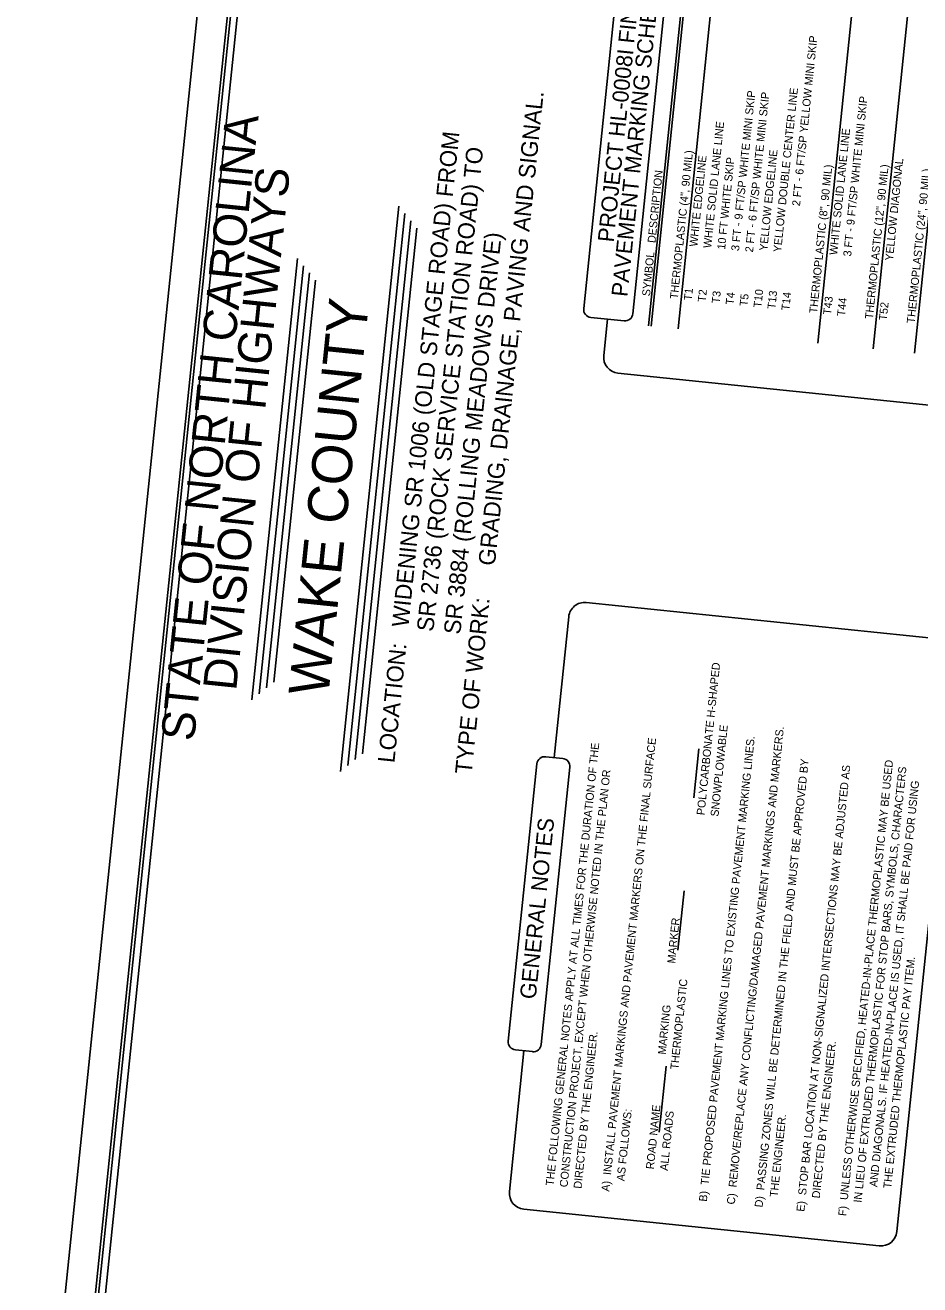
# Model space of a CAD drawing. Extents: x 2077770 to 2079037, y 247476 to 249877.
# Drawn here: x 2077770 to 2078441, y 248438 to 249383 of the extents above; entities that cross this region are included whole.
import ezdxf

# ---------------------------------------------------------------- set-up
doc = ezdxf.new("R2010")
doc.units = 0
for name, color, linetype in [('Default', 7, 'Continuous'), ('Prop DSN Text', 7, 'Continuous'), ('Sheet Data Field CELL', 7, 'Continuous'), ('Sheet Plot Border Inside CELL', 7, 'Continuous'), ('Sheet Plot Border Outside CELL', 7, 'Continuous'), ('Sheet Title CELL', 7, 'Continuous')]:
    doc.layers.add(name, color=color, linetype=linetype)

msp = doc.modelspace()

# ---------------------------------------------------------------- linework, layer by layer
at = {"layer": 'Default'}
for p, q in [((2078237.64, 249157.39), (2078269.5, 249466.05)), ((2078239.63, 249157.18), (2078271.49, 249465.85)), ((2078259.7, 249155.11), (2078291.55, 249463.77)), ((2078364.43, 249144.31), (2078396.28, 249452.98)), ((2078405.9, 249140.03), (2078437.76, 249448.7)), ((2078437.01, 249136.79), (2078468.87, 249445.46))]:
    msp.add_line(p, q, dxfattribs=at)
at = {"layer": 'Prop DSN Text'}
for p, q in [((2078271.44, 248803.43), (2078275.23, 248840.18)), ((2078259.66, 248689.33), (2078264.24, 248733.69)), ((2078245.58, 248552.92), (2078250.69, 248602.37))]:
    msp.add_line(p, q, dxfattribs=at)
at = {"layer": 'Sheet Plot Border Inside CELL'}
msp.add_lwpolyline([(2078843.53, 248043.45), (2079014.62, 249701.14), (2077965.1, 249809.47), (2077794, 248151.77)], close=True, dxfattribs=at)
at = {"layer": 'Sheet Plot Border Outside CELL'}
msp.add_lwpolyline([(2077943.23, 249816.25), (2077770.34, 248141.15), (2078864.51, 248028.21), (2079037.4, 249703.31)], close=True, dxfattribs=at)
at = {"layer": 'Sheet Title CELL'}
for p, q in [((2078188.97, 249170.27), (2078220.83, 249478.94)), ((2078257.71, 249475.14), (2078225.85, 249166.47)), ((2078006.75, 248823.23), (2078050.5, 249246.98)), ((2078012.24, 248827.69), (2078054.96, 249241.49)), ((2078017.74, 248832.15), (2078059.41, 249236)), ((2078023.21, 248836.61), (2078063.88, 249230.52)), ((2077940.33, 248876.98), (2077974.48, 249207.97)), ((2077945.81, 248881.44), (2077978.95, 249202.49)), ((2077951.3, 248885.9), (2077983.4, 249197)), ((2077956.79, 248890.36), (2077987.86, 249191.51)), ((2078194.32, 249163.7), (2078219.27, 249161.12)), ((2078203.98, 249135.1), (2078206.79, 249162.41)), ((2078214.68, 249121.93), (2078581.25, 249084.28)), ((2078190.95, 248949.99), (2078457.5, 248922.48)), ((2078177.78, 248939.29), (2078166.88, 248833.69)), ((2078468.2, 248909.31), (2078423.72, 248478.31)), ((2078160.49, 248834.35), (2078173.28, 248833.03)), ((2078132.45, 248621.13), (2078153.91, 248829)), ((2078178.63, 248826.45), (2078157.17, 248618.58)), ((2078137.8, 248614.55), (2078150.59, 248613.23)), ((2078133.3, 248508.29), (2078144.2, 248613.89)), ((2078144, 248495.12), (2078410.55, 248467.61))]:
    msp.add_line(p, q, dxfattribs=at)
for points in [[(2077964.81, 249781.85), (2077813.88, 248319.62)], [(2077969.78, 249781.34), (2077824, 248368.84)]]:
    msp.add_lwpolyline(points, dxfattribs=at)
for centre, radius, start, end in [((2078194.94, 249169.66), 6, 174.10721, 264.10721), ((2078219.88, 249167.09), 6, 264.10721, 354.10721), ((2078215.91, 249133.87), 12, 174.10721, 264.10721), ((2078189.72, 248938.06), 12, 84.10721, 174.10721), ((2078159.87, 248828.39), 6, 84.10721, 174.10721), ((2078172.66, 248827.07), 6, 354.10721, 84.10721), ((2078138.42, 248620.51), 6, 174.10721, 264.10721), ((2078151.21, 248619.19), 6, 264.10721, 354.10721), ((2078145.23, 248507.06), 12, 174.10721, 264.10721), ((2078411.78, 248479.54), 12, 264.10721, 354.10721)]:
    msp.add_arc(centre, radius, start, end, dxfattribs=at)

# ---------------------------------------------------------------- texts
at = {"layer": 'Default'}
for s, p in [('PAVEMENT MARKING SCHEDULE', (2078221.66, 249178.8)), ('PROJECT HL-0008I FINAL', (2078211.41, 249219.69))]:
    msp.add_text(s, height=12, rotation=84.10721, dxfattribs=at).set_placement(p)
at = {"layer": 'Prop DSN Text'}
for s, height, rotation, p in [('   2 FT - 6 FT/SP YELLOW MINI SKIP', 6, 84.14501, (2078350.42, 249240.26)), ('T4              3 FT - 9 FT/SP WHITE MINI SKIP', 6, 84.14501, (2078301.3, 249172.92)), ('T5              2 FT - 6 FT/SP WHITE MINI SKIP', 6, 84.14501, (2078311.75, 249171.85)), ('T13             YELLOW DOUBLE CENTER LINE', 6, 84.14501, (2078332.63, 249169.71)), ('T44              3 FT - 9 FT/SP WHITE MINI SKIP', 6, 84.14501, (2078384.84, 249164.35)), ('T2              WHITE SOLID LANE LINE', 6, 84.14501, (2078280.42, 249175.06)), ('T43              WHITE SOLID LANE LINE', 6, 84.14501, (2078374.4, 249165.43)), ('THERMOPLASTIC (4", 90 MIL)', 6, 84.14501, (2078259.54, 249177.2)), ('T1              WHITE EDGELINE', 6, 84.14501, (2078269.98, 249176.13)), ('T10             YELLOW EDGELINE', 6, 84.14501, (2078322.19, 249170.78)), ('T3              10 FT WHITE SKIP', 6, 84.14501, (2078290.86, 249173.99)), ('THERMOPLASTIC (8", 90 MIL)', 6, 84.14501, (2078363.96, 249166.5)), ('THERMOPLASTIC (12", 90 MIL)', 6, 84.14501, (2078405.73, 249162.21)), ('T52              YELLOW DIAGONAL', 6, 84.14501, (2078416.17, 249161.14)), ('SYMBOL   DESCRIPTION', 6, 84.14501, (2078238.65, 249179.35)), ('THERMOPLASTIC (24", 90 MIL)', 6, 84.14501, (2078437.05, 249159)), ('T14', 6, 84.14501, (2078343.07, 249168.64)), ('POLYCARBONATE H-SHAPED', 6, 84.10721, (2078279.51, 248790.28)), ('SNOWPLOWABLE', 6, 84.10721, (2078289.95, 248789.21)), ('C)  REMOVE/REPLACE ANY CONFLICTING/DAMAGED PAVEMENT MARKINGS AND MARKERS.', 6, 84.10721, (2078302.15, 248498.42)), ('THE FOLLOWING GENERAL NOTES APPLY AT ALL TIMES FOR THE DURATION OF THE', 6, 84.10721, (2078166.41, 248512.43)), ('A)  INSTALL PAVEMENT MARKINGS AND PAVEMENT MARKERS ON THE FINAL SURFACE', 6, 84.10721, (2078208.18, 248508.12)), ('B)  TIE PROPOSED PAVEMENT MARKING LINES TO EXISTING PAVEMENT MARKING LINES.', 6, 84.10721, (2078281.27, 248500.57)), ('D)  PASSING ZONES WILL BE DETERMINED IN THE FIELD AND MUST BE APPROVED BY', 6, 84.10721, (2078323.03, 248496.26)), ('F)  UNLESS OTHERWISE SPECIFIED, HEATED-IN-PLACE THERMOPLASTIC MAY BE USED', 6, 84.10721, (2078385.68, 248489.79)), ('CONSTRUCTION PROJECT, EXCEPT WHEN OTHERWISE NOTED IN THE PLAN OR', 6, 84.10721, (2078176.85, 248511.35)), ('E)  STOP BAR LOCATION AT NON-SIGNALIZED INTERSECTIONS MAY BE ADJUSTED AS ', 6, 84.10721, (2078354.36, 248493.03)), ('     IN LIEU OF EXTRUDED THERMOPLASTIC FOR STOP BARS, SYMBOLS, CHARACTERS', 6, 84.10721, (2078396.12, 248488.72)), ('AND DIAGONALS. IF HEATED-IN-PLACE IS USED, IT SHALL BE PAID FOR USING', 6, 84.10721, (2078409.03, 248511.51)), ('GENERAL NOTES', 12, 84.10721, (2078152.99, 248652.16)), ('         ROAD NAME                 MARKING              MARKER', 6, 84.10721, (2078239.5, 248504.88)), ('THE EXTRUDED THERMOPLASTIC PAY ITEM.', 6, 84.10721, (2078419.47, 248510.43)), ('         ALL ROADS              THERMOPLASTIC    ', 6, 84.10721, (2078249.94, 248503.8)), ('DIRECTED BY THE ENGINEER.', 6, 84.10721, (2078187.29, 248510.27)), ('     DIRECTED BY THE ENGINEER. ', 6, 84.10721, (2078364.8, 248491.95)), ('    AS FOLLOWS:', 6, 84.10721, (2078218.62, 248507.04)), ('    THE ENGINEER.', 6, 84.10721, (2078333.48, 248495.18))]:
    msp.add_text(s, height=height, rotation=rotation, dxfattribs=at).set_placement(p)
at = {"layer": 'Sheet Data Field CELL'}
for s, height, p in [('GRADING, DRAINAGE, PAVING AND SIGNAL.', 12.5001, (2078122.39, 248977.15)), ('WIDENING SR 1006 (OLD STAGE ROAD) FROM', 12.5001, (2078057.54, 248931.06)), ('SR 2736 (ROCK SERVICE STATION ROAD) TO', 12.5001, (2078076.27, 248927.74)), ('SR 3884 (ROLLING MEADOWS DRIVE)', 12.5001, (2078096.48, 248925.65)), ('WAKE COUNTY', 30, (2077997.53, 248879.07))]:
    msp.add_text(s, height=height, rotation=84.10721, dxfattribs=at).set_placement(p)
at = {"layer": 'Sheet Title CELL'}
for s, height, p in [('STATE OF NORTH CAROLINA', 24.9999, (2077896.9, 248845.43)), ('DIVISION OF HIGHWAYS', 24.9999, (2077928.46, 248883.34)), ('TYPE OF WORK:', 12.5001, (2078104.93, 248820.92)), ('LOCATION: ', 12.5, (2078047.04, 248829.32))]:
    msp.add_text(s, height=height, rotation=84.10721, dxfattribs=at).set_placement(p)

doc.saveas('drawing.dxf')
